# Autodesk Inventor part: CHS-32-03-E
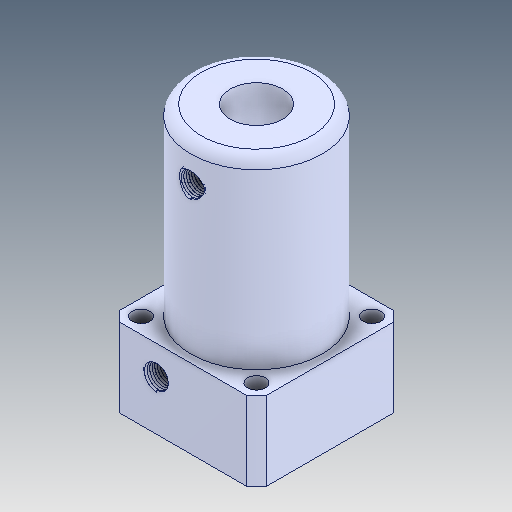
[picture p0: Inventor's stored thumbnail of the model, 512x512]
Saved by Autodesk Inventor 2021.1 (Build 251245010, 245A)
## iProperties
Created: 2021-05
Part Number: CHS-32-03-E
Material: Ogólny
Document SubType Name: Modeling
Designer: user
Density: 1 g/cm^3
Appearance: Domyślna
Author: user
Revision Number: ÈÎºÎ
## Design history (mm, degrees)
feature "NONE"
node "Bryła1"
